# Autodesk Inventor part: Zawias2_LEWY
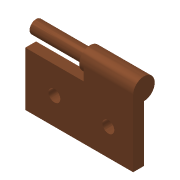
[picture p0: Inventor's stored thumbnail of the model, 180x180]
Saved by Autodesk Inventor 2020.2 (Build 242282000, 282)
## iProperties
Created: 2005-09
Part Number: Zawias2_LEWY
Material: Ogólny
Document SubType Name: Modeling
Designer: F.Stasiak
Mass: 8.92117 g
Surface Area: 46.2756 cm^2
Volume: 8.92117 cm^3
Density: 1 g/cm^3
Appearance: Domyślna
Manager: www.cadconsulting.pl
Company: Fabian Stasiak CAD Consulting
d0: 50,000 mm
d2: 23,000 mm
d4: 5,000 mm
d5: 0,00 deg
d7: 0,00 deg
d9: 6,000 mm
d10: 25,000 mm
d11: 0,00 deg
d12: 5,500 mm
d20: 25,000 mm
d21: 6,000 mm
d22: 10,000 mm
Author: F.Stasiak
Subject: Zbiór ćwiczeń. Autodesk Inventor 2020. Kurs podstawowy
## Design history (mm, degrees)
derived "Zawias2.ipt"
  sketch "Szkic1"
    geometry: L1 (-2, 31)-(-25, 31) reference; L2 (-25, 31)-(-25, 0) reference; L3 (-25, 0)-(25, 0) reference; L4 (25, 0)-(25, 25) reference; L5 (25, 25)-(-2, 25) reference; L6 (-2, 25)-(-2, 31) reference; 2 further points
  sketch "Szkic2"
    geometry: L1 (0, 0)-(0, 6) reference; L2 (-5, 0)-(-5, 6) reference; C1 r 5 at (-5, 6) reference
  sketch "Szkic3"
    geometry: C1 r 5 at (0, 0) reference; C2 r 3 at (0, 0) reference
  sketch "Szkic4"
    geometry: L1 (25, 0)-(25, 25) reference; L2 (-25, 26)-(-25, 0) reference; L3 (-25, 26)-(-2, 26) reference; L4 (25, 25)-(-2, 25) reference; L5 (25, 12.5)-(-25, 12.5) reference; L6 (11.5, 25)-(11.5, 12.5) reference; L7 (-13.5, 26)-(-13.5, 12.5) reference
feature "Bryła1::Zawias2.ipt"
tag "Bryła wyprowadzona1"
node "Bryła1"
other parameters: "d0" = 10, "d2" = 23, "d4" = 5, "d5" = 0 deg, "d7" = 0 deg, "d9" = 6, "d10" = 25, "d11" = 0 deg, "d12" = 5.5, "d20" = 25, "d21" = 6, "d22" = 10
